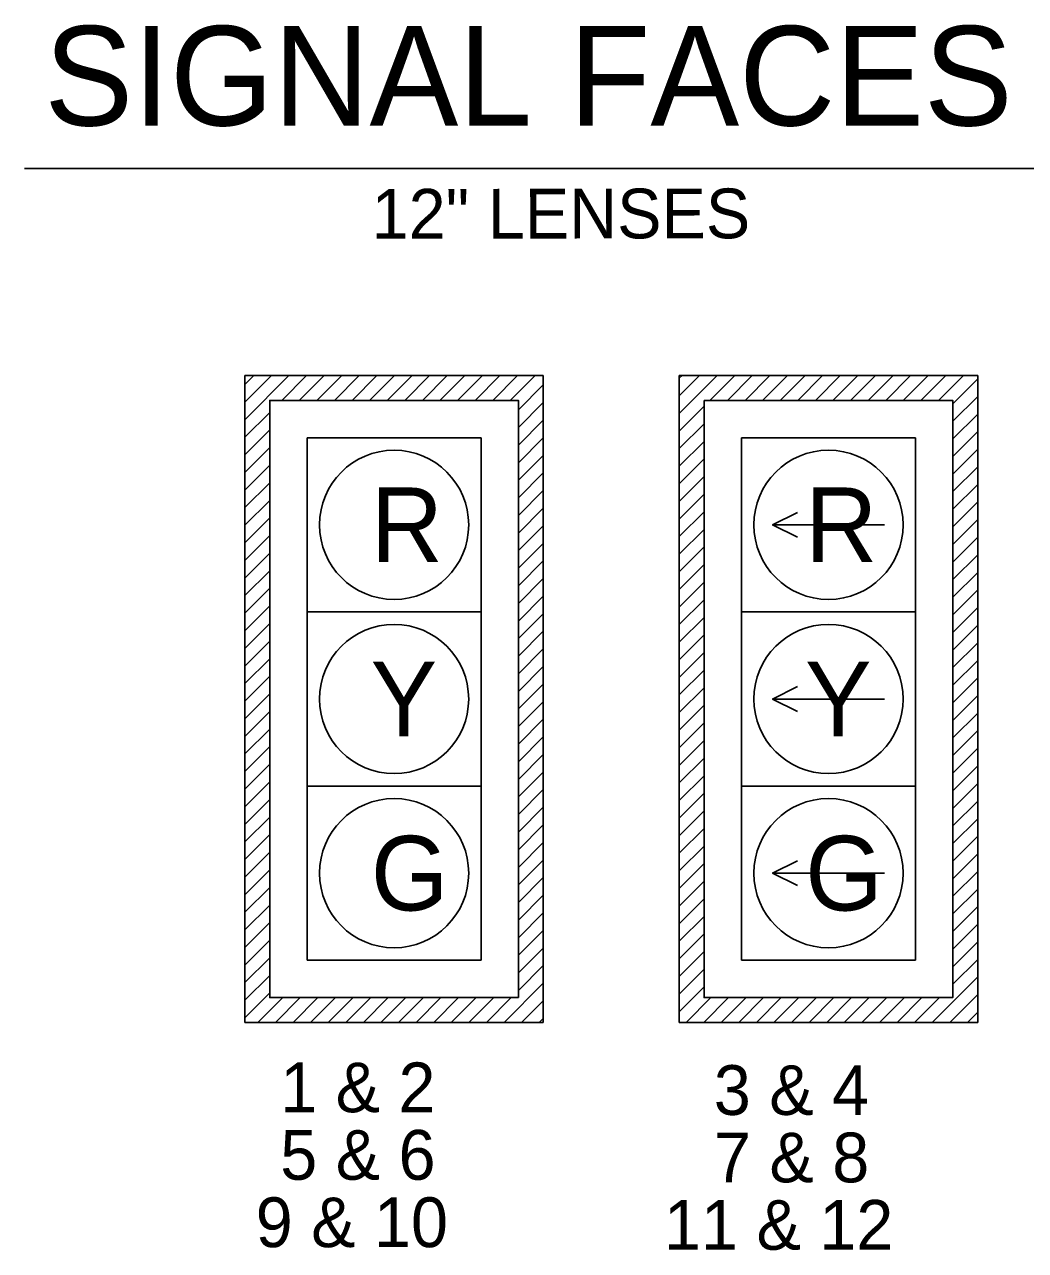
# Model space of a CAD drawing. Extents: x -15.7 to 19.3, y -1.4 to 10.8.
# Drawn here: x 6.383 to 7.725, y 9.061 to 10.704 of the extents above; entities that cross this region are included whole.
import ezdxf

# ---------------------------------------------------------------- set-up
doc = ezdxf.new("R2010")
doc.units = 0
doc.layers.add('T_Drafting', color=7, linetype='Continuous')
doc.layers.add('T_Notes', color=7, linetype='Continuous')

msp = doc.modelspace()

# ---------------------------------------------------------------- linework, layer by layer
at = {"layer": 'T_Drafting'}
for p, q in [((7.0783, 10.2334), (6.6783, 10.2334)), ((6.6783, 10.2334), (6.6783, 9.3668)), ((6.6783, 10.1743), (6.7374, 10.2334)), ((6.6783, 10.1979), (6.7138, 10.2334)), ((6.6783, 10.2215), (6.6902, 10.2334)), ((6.7276, 10.2001), (6.7609, 10.2334)), ((6.7512, 10.2001), (6.7845, 10.2334)), ((6.7748, 10.2001), (6.8081, 10.2334)), ((6.7983, 10.2001), (6.8317, 10.2334)), ((6.8219, 10.2001), (6.8552, 10.2334)), ((6.8455, 10.2001), (6.8788, 10.2334)), ((6.869, 10.2001), (6.9024, 10.2334)), ((6.8926, 10.2001), (6.9259, 10.2334)), ((6.9162, 10.2001), (6.9495, 10.2334)), ((6.9397, 10.2001), (6.9731, 10.2334)), ((6.9633, 10.2001), (6.9967, 10.2334)), ((6.9869, 10.2001), (7.0202, 10.2334)), ((7.0105, 10.2001), (7.0438, 10.2334)), ((7.034, 10.2001), (7.0674, 10.2334)), ((7.0783, 9.3668), (7.0783, 10.2334)), ((7.2606, 10.2334), (7.6606, 10.2334)), ((7.2606, 9.3668), (7.2606, 10.2334)), ((7.2606, 10.1826), (7.3114, 10.2334)), ((7.2606, 10.2062), (7.2878, 10.2334)), ((7.2606, 10.2298), (7.2643, 10.2334)), ((7.3016, 10.2001), (7.335, 10.2334)), ((7.3252, 10.2001), (7.3585, 10.2334)), ((7.3488, 10.2001), (7.3821, 10.2334)), ((7.3723, 10.2001), (7.4057, 10.2334)), ((7.3959, 10.2001), (7.4292, 10.2334)), ((7.4195, 10.2001), (7.4528, 10.2334)), ((7.4431, 10.2001), (7.4764, 10.2334)), ((7.4666, 10.2001), (7.5, 10.2334)), ((7.4902, 10.2001), (7.5235, 10.2334)), ((7.5138, 10.2001), (7.5471, 10.2334)), ((7.5373, 10.2001), (7.5707, 10.2334)), ((7.5609, 10.2001), (7.5942, 10.2334)), ((7.5845, 10.2001), (7.6178, 10.2334)), ((7.608, 10.2001), (7.6414, 10.2334)), ((7.6606, 10.2334), (7.6606, 9.3668)), ((7.0449, 10.1874), (7.0783, 10.2208)), ((7.6272, 10.1957), (7.6606, 10.2291)), ((7.6272, 10.1722), (7.6606, 10.2055)), ((6.6783, 10.1508), (6.7116, 10.1841)), ((7.0449, 10.1639), (7.0783, 10.1972)), ((7.2606, 10.159), (7.2939, 10.1924)), ((7.0449, 10.1403), (7.0783, 10.1736)), ((7.2606, 10.1355), (7.2939, 10.1688)), ((7.6272, 10.1486), (7.6606, 10.1819)), ((6.6783, 10.1272), (6.7116, 10.1605)), ((6.7616, 10.1501), (6.9949, 10.1501)), ((6.7616, 10.1501), (6.7616, 9.9168)), ((6.9949, 10.1501), (6.9949, 9.9168)), ((7.0449, 10.1167), (7.0783, 10.1501)), ((7.3439, 10.1501), (7.5772, 10.1501)), ((7.3439, 10.1501), (7.3439, 9.9168)), ((7.5772, 10.1501), (7.5772, 9.9168)), ((7.6272, 10.125), (7.6606, 10.1584)), ((6.6783, 10.1036), (6.7116, 10.137)), ((7.2606, 10.1119), (7.2939, 10.1452)), ((7.6272, 10.1014), (7.6606, 10.1348)), ((7.0449, 10.0932), (7.0783, 10.1265)), ((7.2606, 10.0883), (7.2939, 10.1217)), ((6.6783, 10.0801), (6.7116, 10.1134)), ((7.0449, 10.0696), (7.0783, 10.1029)), ((7.6272, 10.0779), (7.6606, 10.1112)), ((6.6783, 10.0565), (6.7116, 10.0898)), ((7.2606, 10.0648), (7.2939, 10.0981)), ((7.6272, 10.0543), (7.6606, 10.0876)), ((7.0449, 10.046), (7.0783, 10.0794)), ((7.2606, 10.0412), (7.2939, 10.0745)), ((6.6783, 10.0329), (6.7116, 10.0662)), ((7.0449, 10.0225), (7.0783, 10.0558)), ((7.6272, 10.0307), (7.6606, 10.0641)), ((6.6783, 10.0093), (6.7116, 10.0427)), ((7.2606, 10.0176), (7.2939, 10.051)), ((7.6272, 10.0072), (7.6606, 10.0405)), ((6.6783, 9.9858), (6.7116, 10.0191)), ((7.0449, 9.9989), (7.0783, 10.0322)), ((7.2606, 9.9941), (7.2939, 10.0274)), ((7.5356, 10.0334), (7.3856, 10.0334)), ((7.0449, 9.9753), (7.0783, 10.0086)), ((7.2606, 9.9705), (7.2939, 10.0038)), ((7.6272, 9.9836), (7.6606, 10.0169)), ((6.6783, 9.9622), (6.7116, 9.9955)), ((7.6272, 9.96), (7.6606, 9.9934)), ((6.6783, 9.9386), (6.7116, 9.972)), ((7.0449, 9.9517), (7.0783, 9.9851)), ((7.2606, 9.9469), (7.2939, 9.9802)), ((7.6272, 9.9365), (7.6606, 9.9698)), ((7.0449, 9.9282), (7.0783, 9.9615)), ((7.2606, 9.9233), (7.2939, 9.9567)), ((6.6783, 9.9151), (6.7116, 9.9484)), ((7.0449, 9.9046), (7.0783, 9.9379)), ((7.6272, 9.9129), (7.6606, 9.9462)), ((6.6783, 9.8915), (6.7116, 9.9248)), ((7.2606, 9.8998), (7.2939, 9.9331)), ((7.6272, 9.8893), (7.6606, 9.9226)), ((6.7616, 9.9168), (6.9949, 9.9168)), ((6.7616, 9.9168), (6.7616, 9.6834)), ((6.9949, 9.9168), (6.9949, 9.6834)), ((7.0449, 9.881), (7.0783, 9.9144)), ((7.2606, 9.8762), (7.2939, 9.9095)), ((7.3439, 9.9168), (7.5772, 9.9168)), ((7.3439, 9.9168), (7.3439, 9.6834)), ((7.5772, 9.9168), (7.5772, 9.6834)), ((6.6783, 9.8679), (6.7116, 9.9013)), ((7.0449, 9.8575), (7.0783, 9.8908)), ((7.6272, 9.8657), (7.6606, 9.8991)), ((6.6783, 9.8443), (6.7116, 9.8777)), ((7.2606, 9.8526), (7.2939, 9.886)), ((7.6272, 9.8422), (7.6606, 9.8755)), ((7.0449, 9.8339), (7.0783, 9.8672)), ((7.2606, 9.8291), (7.2939, 9.8624)), ((6.6783, 9.8208), (6.7116, 9.8541)), ((7.0449, 9.8103), (7.0783, 9.8437)), ((7.2606, 9.8055), (7.2939, 9.8388)), ((7.6272, 9.8186), (7.6606, 9.8519)), ((6.6783, 9.7972), (6.7116, 9.8305)), ((7.6272, 9.795), (7.6606, 9.8284)), ((6.6783, 9.7736), (6.7116, 9.807)), ((7.0449, 9.7868), (7.0783, 9.8201)), ((7.2606, 9.7819), (7.2939, 9.8153)), ((7.0449, 9.7632), (7.0783, 9.7965)), ((7.2606, 9.7584), (7.2939, 9.7917)), ((7.5356, 9.8001), (7.3856, 9.8001)), ((7.6272, 9.7715), (7.6606, 9.8048)), ((6.6783, 9.7501), (6.7116, 9.7834)), ((7.0449, 9.7396), (7.0783, 9.7729)), ((7.6272, 9.7479), (7.6606, 9.7812)), ((6.6783, 9.7265), (6.7116, 9.7598)), ((7.2606, 9.7348), (7.2939, 9.7681)), ((7.6272, 9.7243), (7.6606, 9.7577)), ((7.0449, 9.716), (7.0783, 9.7494)), ((7.2606, 9.7112), (7.2939, 9.7445)), ((6.6783, 9.7029), (6.7116, 9.7363)), ((7.0449, 9.6925), (7.0783, 9.7258)), ((7.6272, 9.7008), (7.6606, 9.7341)), ((6.6783, 9.6794), (6.7116, 9.7127)), ((7.2606, 9.6876), (7.2939, 9.721)), ((7.6272, 9.6772), (7.6606, 9.7105)), ((7.0449, 9.6689), (7.0783, 9.7022)), ((7.2606, 9.6641), (7.2939, 9.6974)), ((6.6783, 9.6558), (6.7116, 9.6891)), ((6.7616, 9.6834), (6.9949, 9.6834)), ((6.7616, 9.6834), (6.7616, 9.4501)), ((6.9949, 9.6834), (6.9949, 9.4501)), ((7.0449, 9.6453), (7.0783, 9.6787)), ((7.2606, 9.6405), (7.2939, 9.6738)), ((7.3439, 9.6834), (7.5772, 9.6834)), ((7.3439, 9.6834), (7.3439, 9.4501)), ((7.5772, 9.6834), (7.5772, 9.4501)), ((7.6272, 9.6536), (7.6606, 9.6869)), ((6.6783, 9.6322), (6.7116, 9.6656)), ((7.6272, 9.63), (7.6606, 9.6634)), ((6.6783, 9.6086), (6.7116, 9.642)), ((7.0449, 9.6218), (7.0783, 9.6551)), ((7.2606, 9.6169), (7.2939, 9.6503)), ((7.0449, 9.5982), (7.0783, 9.6315)), ((7.2606, 9.5934), (7.2939, 9.6267)), ((7.6272, 9.6065), (7.6606, 9.6398)), ((6.6783, 9.5851), (6.7116, 9.6184)), ((7.6272, 9.5829), (7.6606, 9.6162)), ((6.6783, 9.5615), (6.7116, 9.5948)), ((7.0449, 9.5746), (7.0783, 9.608)), ((7.2606, 9.5698), (7.2939, 9.6031)), ((7.6272, 9.5593), (7.6606, 9.5927)), ((7.0449, 9.5511), (7.0783, 9.5844)), ((7.2606, 9.5462), (7.2939, 9.5796)), ((6.6783, 9.5379), (6.7116, 9.5713)), ((7.0449, 9.5275), (7.0783, 9.5608)), ((7.5356, 9.5668), (7.3856, 9.5668)), ((7.6272, 9.5358), (7.6606, 9.5691)), ((6.6783, 9.5144), (6.7116, 9.5477)), ((7.2606, 9.5226), (7.2939, 9.556)), ((7.6272, 9.5122), (7.6606, 9.5455)), ((7.0449, 9.5039), (7.0783, 9.5372)), ((7.2606, 9.4991), (7.2939, 9.5324)), ((6.6783, 9.4908), (6.7116, 9.5241)), ((7.0449, 9.4803), (7.0783, 9.5137)), ((7.6272, 9.4886), (7.6606, 9.522)), ((6.6783, 9.4672), (6.7116, 9.5006)), ((7.2606, 9.4755), (7.2939, 9.5088)), ((7.6272, 9.4651), (7.6606, 9.4984)), ((6.6783, 9.4437), (6.7116, 9.477)), ((7.0449, 9.4568), (7.0783, 9.4901)), ((7.2606, 9.4519), (7.2939, 9.4853)), ((7.0449, 9.4332), (7.0783, 9.4665)), ((7.2606, 9.4284), (7.2939, 9.4617)), ((7.6272, 9.4415), (7.6606, 9.4748)), ((6.6783, 9.4201), (6.7116, 9.4534)), ((6.7616, 9.4501), (6.9949, 9.4501)), ((7.3439, 9.4501), (7.5772, 9.4501)), ((7.6272, 9.4179), (7.6606, 9.4512)), ((6.6783, 9.3965), (6.7116, 9.4298)), ((7.0449, 9.4096), (7.0783, 9.443)), ((7.2606, 9.4048), (7.2939, 9.4381)), ((7.5997, 9.3668), (7.6606, 9.4277)), ((7.0257, 9.3668), (7.0783, 9.4194)), ((7.2606, 9.3812), (7.2939, 9.4146)), ((6.6783, 9.3729), (6.7116, 9.4063)), ((6.6957, 9.3668), (6.729, 9.4001)), ((6.7192, 9.3668), (6.7526, 9.4001)), ((6.7428, 9.3668), (6.7761, 9.4001)), ((6.7664, 9.3668), (6.7997, 9.4001)), ((6.79, 9.3668), (6.8233, 9.4001)), ((6.8135, 9.3668), (6.8469, 9.4001)), ((6.8371, 9.3668), (6.8704, 9.4001)), ((6.8607, 9.3668), (6.894, 9.4001)), ((6.8842, 9.3668), (6.9176, 9.4001)), ((6.9078, 9.3668), (6.9411, 9.4001)), ((6.9314, 9.3668), (6.9647, 9.4001)), ((6.9549, 9.3668), (6.9883, 9.4001)), ((6.9785, 9.3668), (7.0118, 9.4001)), ((7.0021, 9.3668), (7.0354, 9.4001)), ((7.0492, 9.3668), (7.0783, 9.3958)), ((7.2697, 9.3668), (7.303, 9.4001)), ((7.2933, 9.3668), (7.3266, 9.4001)), ((7.3168, 9.3668), (7.3502, 9.4001)), ((7.3404, 9.3668), (7.3737, 9.4001)), ((7.364, 9.3668), (7.3973, 9.4001)), ((7.3875, 9.3668), (7.4209, 9.4001)), ((7.4111, 9.3668), (7.4444, 9.4001)), ((7.4347, 9.3668), (7.468, 9.4001)), ((7.4582, 9.3668), (7.4916, 9.4001)), ((7.4818, 9.3668), (7.5152, 9.4001)), ((7.5054, 9.3668), (7.5387, 9.4001)), ((7.529, 9.3668), (7.5623, 9.4001)), ((7.5525, 9.3668), (7.5859, 9.4001)), ((7.5761, 9.3668), (7.6094, 9.4001)), ((7.6232, 9.3668), (7.6606, 9.4041)), ((7.6468, 9.3668), (7.6606, 9.3805)), ((6.6783, 9.3668), (7.0783, 9.3668)), ((7.0728, 9.3668), (7.0783, 9.3723)), ((7.6606, 9.3668), (7.2606, 9.3668))]:
    msp.add_line(p, q, dxfattribs=at)
for points in [[(7.0449, 9.4001), (7.0449, 10.2001), (6.7116, 10.2001), (6.7116, 9.4001)], [(7.2939, 10.2001), (7.6272, 10.2001), (7.6272, 9.4001), (7.2939, 9.4001)]]:
    msp.add_lwpolyline(points, close=True, dxfattribs=at)
for points in [[(7.4189, 10.0501), (7.3856, 10.0334), (7.4189, 10.0168)], [(7.4189, 9.8168), (7.3856, 9.8001), (7.4189, 9.7834)], [(7.4189, 9.5834), (7.3856, 9.5668), (7.4189, 9.5501)]]:
    msp.add_lwpolyline(points, dxfattribs=at)
for centre in [(6.8783, 10.0334), (7.4606, 10.0334), (6.8783, 9.8001), (7.4606, 9.8001), (6.8783, 9.5668), (7.4606, 9.5668)]:
    msp.add_circle(centre, 0.1, dxfattribs=at)
at = {"layer": 'T_Notes'}
msp.add_line((6.3829, 10.5106), (8.0193, 10.5106), dxfattribs=at)

# ---------------------------------------------------------------- texts
at = {"layer": 'T_Drafting'}
msp.add_text('12" LENSES', height=0.06667, rotation=0.072, dxfattribs=at).set_placement((6.8483, 10.4167))
for s, p in [('R', (6.8472, 9.9835)), ('R', (7.4295, 9.9835)), ('Y', (6.8468, 9.7501)), ('Y', (7.4291, 9.7501)), ('G', (6.8472, 9.5168)), ('G', (7.4295, 9.5168))]:
    msp.add_text(s, height=0.1, dxfattribs=at).set_placement(p)
at = {"layer": 'T_Notes'}
for s, height, p in [('SIGNAL FACES', 0.133333, (6.4095, 10.5684)), ('1 & 2', 0.06667, (6.7256, 9.2465)), ('3 & 4', 0.06667, (7.3069, 9.2429)), ('5 & 6', 0.06667, (6.7257, 9.1561)), ('7 & 8', 0.06667, (7.3071, 9.1526)), ('9 & 10', 0.06667, (6.6928, 9.0658)), ('11 & 12', 0.06667, (7.2402, 9.0623))]:
    msp.add_text(s, height=height, dxfattribs=at).set_placement(p)

doc.saveas('drawing.dxf')
